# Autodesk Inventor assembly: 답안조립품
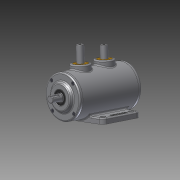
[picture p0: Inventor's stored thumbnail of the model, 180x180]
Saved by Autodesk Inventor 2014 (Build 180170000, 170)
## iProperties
Created: 2014-12
Part Number: 답안조립품
Document SubType Name: Assembly
Designer: Owner
Author: Owner
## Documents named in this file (10)
- C:\Users\Owner\Desktop\441223V1003\답안조립품.iam
- C:\Users\Owner\Desktop\441223V1003\1.본체.ipt
- C:\Users\Owner\Desktop\441223V1003\4.축.ipt
- C:\Users\Owner\Desktop\441223V1003\M4-소켓머리.ipt
- C:\Users\Owner\Desktop\441223V1003\뒷커버.ipt
- C:\Users\Owner\Desktop\441223V1003\베어링 6203.ipt
- C:\Users\Owner\Desktop\441223V1003\부시.ipt
- C:\Users\Owner\Desktop\441223V1003\슬라이더.ipt
- C:\Users\Owner\Desktop\441223V1003\앞커버.ipt
- C:\Users\Owner\Desktop\441223V1003\오일실.ipt
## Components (12 placed, 5 different names)
1. 1.본체:1
2. 4.축:1
3. 7-베어링 6203:1
4. 8-오일실:1
5. 9-M4-소켓머리:2
6. 9-M4-소켓머리:3
7. 9-M4-소켓머리:4
8. 9-M4-소켓머리:5
9. 9-M4-소켓머리:1
10. 9-M4-소켓머리:6
11. 9-M4-소켓머리:7
12. 9-M4-소켓머리:8
